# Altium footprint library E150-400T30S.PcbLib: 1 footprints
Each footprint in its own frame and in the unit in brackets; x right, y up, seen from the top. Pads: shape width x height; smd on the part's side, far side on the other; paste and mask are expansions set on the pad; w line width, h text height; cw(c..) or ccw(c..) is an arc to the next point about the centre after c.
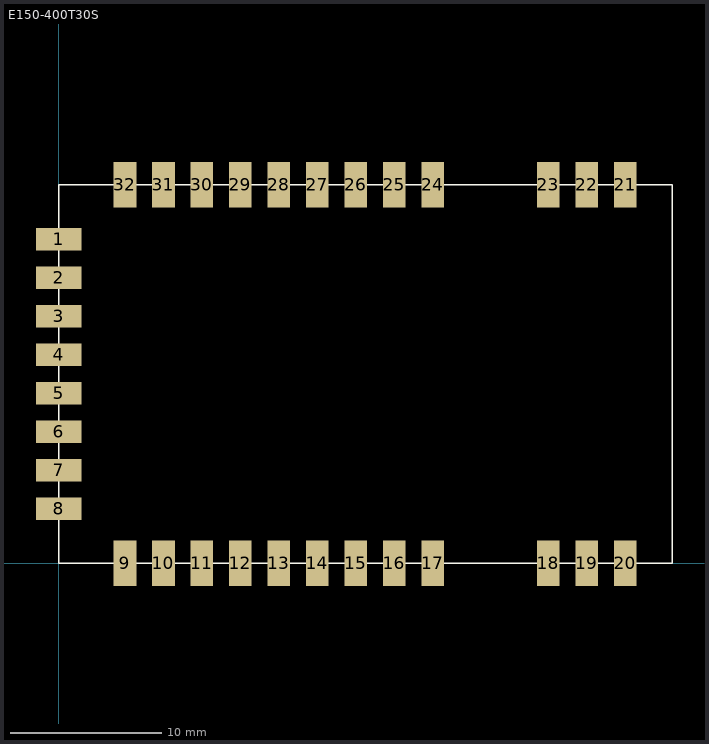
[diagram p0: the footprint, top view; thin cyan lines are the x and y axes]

## E150-400T30S [mm]
pads (32):
  rect 3x1.5 smd: 1(0,21.39) 2(0,18.85) 3(0,16.31) 4(0,13.77) 5(0,11.23) 6(0,8.69) 7(0,6.15) 8(0,3.61)
  rect 1.5x3 smd: 9(4.38,0) 10(6.92,0) 11(9.46,0) 12(12,0) 13(14.54,0) 14(17.08,0) 15(19.62,0) 16(22.16,0) 17(24.7,0) 18(32.32,0) 19(34.86,0) 20(37.4,0) 21(37.4,25) 22(34.86,25) 23(32.32,25) 24(24.7,25) 25(22.16,25) 26(19.62,25) 27(17.08,25) 28(14.54,25) 29(12,25) 30(9.46,25) 31(6.92,25) 32(4.38,25)
Top Overlay:
  lines w0.1: 0,0 40.5,0 40.5,25 0,25 0,0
